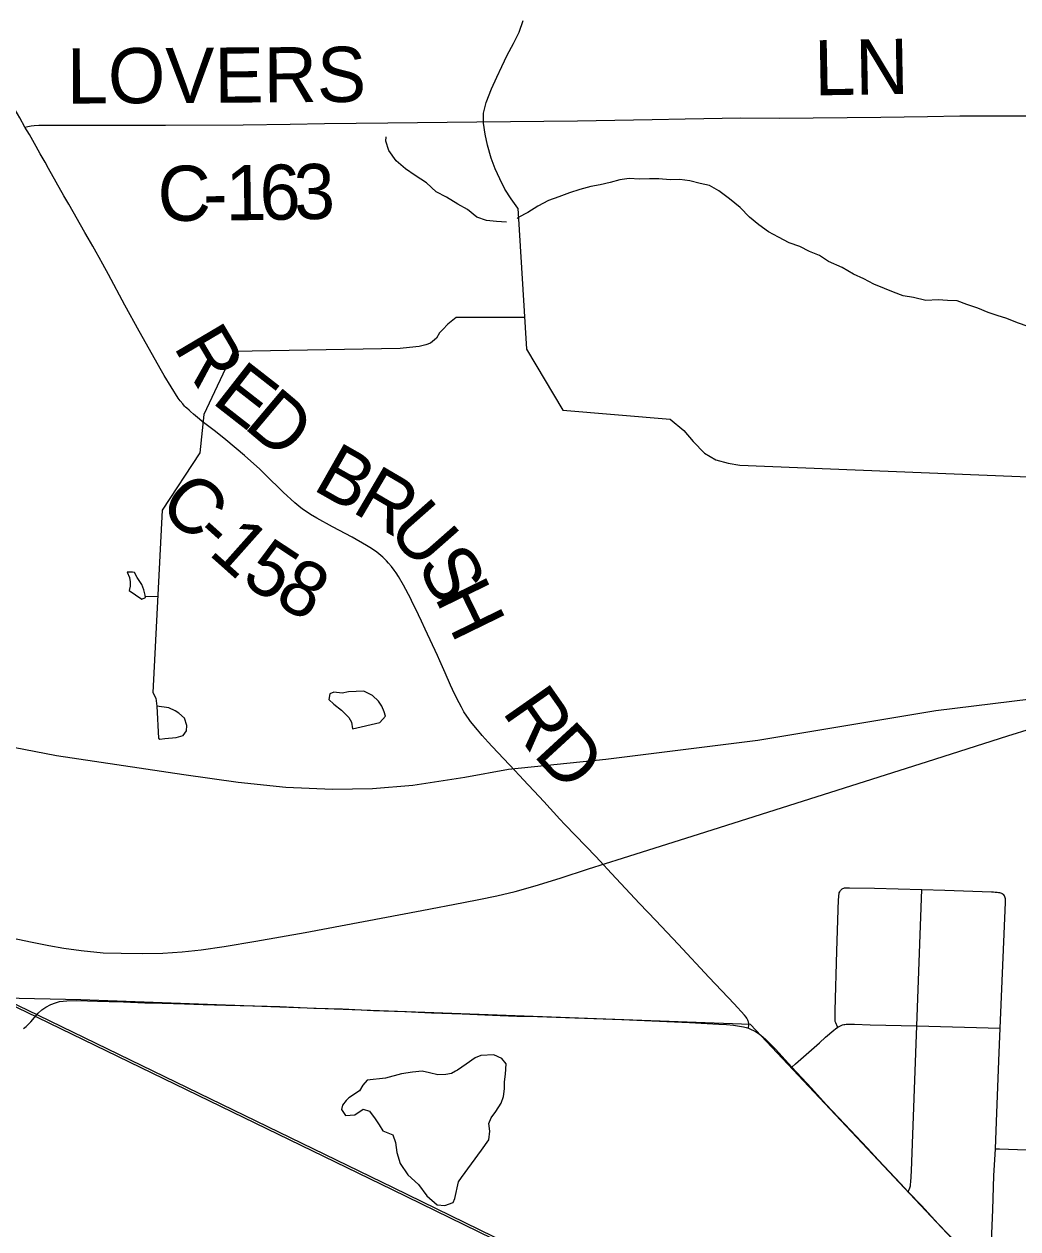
# Model space of a CAD drawing. Extents: x 0 to 34, y 0 to 22.
# Drawn here: x 5.317 to 6.341, y 14.44 to 15.681 of the extents above; entities that cross this region are included whole.
import ezdxf

# ---------------------------------------------------------------- set-up
doc = ezdxf.new("R2010")
doc.units = 0
for name, color, linetype in [('GM_X_County_Road', 7, 'Continuous'), ('GM_X_County_Road_Text', 7, 'Continuous'), ('GM_X_Minor_Lake', 7, 'Continuous'), ('GM_X_Minor_River', 7, 'Continuous'), ('GM_X_Rail_Line', 7, 'Continuous'), ('GM_X_Township_Road', 7, 'Continuous')]:
    doc.layers.add(name, color=color, linetype=linetype)

msp = doc.modelspace()

# ---------------------------------------------------------------- linework, layer by layer
at = {"layer": 'GM_X_County_Road'}
for points in [[(5.3182, 15.5753), (5.3128, 15.5847), (5.3057, 15.5971), (5.3003, 15.6068), (5.294, 15.6182), (5.2866, 15.6319), (5.2773, 15.6486), (5.261, 15.6776), (5.2575, 15.6842)], [(5.3182, 15.5753), (5.321, 15.576), (5.3244, 15.5766), (5.3277, 15.5769), (5.3323, 15.5771), (5.3412, 15.5773), (5.3605, 15.5773), (5.463, 15.5772), (5.5429, 15.5774), (5.5915, 15.5782), (5.6269, 15.5788), (5.692, 15.5797), (5.7838, 15.5806), (5.8876, 15.5817), (5.9643, 15.5831), (5.9983, 15.5838), (6.0558, 15.5848), (6.0955, 15.5846), (6.2, 15.5856), (6.2482, 15.5863), (6.2816, 15.5867), (6.3406, 15.587), (6.3728, 15.5869)], [(5.7955, 14.9418), (5.7924, 14.9451), (5.7894, 14.9485), (5.7879, 14.9501), (5.7845, 14.9542), (5.7773, 14.9631), (5.7752, 14.9659), (5.7734, 14.9684), (5.7705, 14.973), (5.7679, 14.9777), (5.7655, 14.9821), (5.7622, 14.9886), (5.7588, 14.996), (5.7567, 15.0005), (5.7513, 15.013), (5.7458, 15.0253), (5.7431, 15.031), (5.7306, 15.0582), (5.7268, 15.0664), (5.7205, 15.0794), (5.7173, 15.0859), (5.7157, 15.0893), (5.7083, 15.1033), (5.703, 15.1124), (5.7005, 15.1162), (5.6987, 15.1187), (5.6959, 15.1225), (5.6929, 15.1261), (5.6906, 15.1286), (5.6868, 15.1323), (5.6806, 15.1375), (5.6754, 15.1411), (5.6701, 15.1444), (5.6555, 15.1527), (5.6351, 15.1634), (5.6188, 15.1723), (5.6125, 15.1761), (5.6079, 15.1791), (5.6043, 15.1816), (5.6004, 15.1847), (5.5961, 15.1882), (5.5843, 15.1992), (5.5658, 15.2175), (5.5603, 15.2227), (5.5443, 15.237), (5.5252, 15.2531), (5.5145, 15.2617), (5.5009, 15.2721), (5.4981, 15.2743), (5.4918, 15.2795), (5.4888, 15.2822), (5.4872, 15.2836), (5.485, 15.2856), (5.4835, 15.2869), (5.4827, 15.2878), (5.4808, 15.29), (5.4782, 15.2931), (5.4762, 15.2959), (5.4615, 15.3195), (5.4588, 15.3241), (5.4357, 15.365), (5.4211, 15.3917), (5.4042, 15.4235), (5.3984, 15.4342), (5.3946, 15.441), (5.3916, 15.4465), (5.3881, 15.4526), (5.3833, 15.4609), (5.38, 15.4668), (5.3633, 15.4959), (5.3583, 15.5045), (5.3425, 15.5327), (5.3389, 15.5392), (5.334, 15.5477), (5.3298, 15.5552), (5.3227, 15.5675), (5.3182, 15.5753)], [(5.8274, 14.9077), (5.8231, 14.9125), (5.8175, 14.9184), (5.7996, 14.9373), (5.7955, 14.9418)], [(6.0636, 14.6469), (6.0639, 14.6504), (6.0639, 14.6519), (6.0636, 14.6535), (6.0634, 14.6544), (6.0631, 14.6553), (6.0628, 14.656), (6.0624, 14.6567), (6.062, 14.6573), (6.0612, 14.6584), (6.0596, 14.6603), (6.0488, 14.672), (6.0232, 14.6993), (5.9912, 14.7336), (5.9682, 14.7581), (5.9515, 14.7754), (5.9225, 14.8062), (5.9107, 14.8194), (5.9065, 14.8239), (5.896, 14.8344), (5.8743, 14.857), (5.8693, 14.8624), (5.8527, 14.8805), (5.8428, 14.8912), (5.8367, 14.8978), (5.8274, 14.9077)], [(5.3167, 14.6468), (5.3193, 14.6488), (5.3241, 14.6536), (5.3319, 14.6624), (5.3357, 14.6659), (5.3398, 14.6688), (5.3449, 14.6715), (5.3496, 14.6733), (5.3539, 14.6744), (5.3574, 14.675), (5.3614, 14.6753), (5.3714, 14.6757), (5.3827, 14.6752), (5.3928, 14.675), (5.405, 14.6745), (5.4198, 14.6741), (5.4416, 14.6732), (5.4596, 14.6727), (5.4826, 14.672), (5.5019, 14.6715), (5.5252, 14.6709), (5.5546, 14.6701), (5.5808, 14.6692), (5.616, 14.6678), (5.6454, 14.6668), (5.6773, 14.6653), (5.7096, 14.6641), (5.737, 14.6629), (5.7686, 14.6617), (5.8077, 14.66), (5.8251, 14.6595), (5.8462, 14.6589), (5.9332, 14.6558), (6.0028, 14.6528), (6.0332, 14.6513), (6.0412, 14.6507), (6.0481, 14.6501), (6.0524, 14.6496), (6.0564, 14.6489), (6.0587, 14.6484), (6.0612, 14.6478), (6.0636, 14.6469)], [(6.0636, 14.6469), (6.0664, 14.6457), (6.0688, 14.6446), (6.071, 14.6435), (6.0736, 14.6418), (6.0763, 14.6399), (6.0816, 14.6355), (6.0916, 14.6253), (6.1085, 14.607)], [(6.1085, 14.607), (6.1287, 14.5851), (6.1437, 14.5685), (6.1689, 14.542), (6.186, 14.5239), (6.1978, 14.5111), (6.2203, 14.4871), (6.2284, 14.4786)], [(6.2284, 14.4786), (6.2419, 14.4643), (6.2593, 14.4456), (6.2879, 14.4156), (6.3108, 14.3914)]]:
    msp.add_lwpolyline(points, dxfattribs=at)
at = {"layer": 'GM_X_Minor_Lake'}
for p, q in [((5.4257, 15.098), (5.4386, 15.089)), ((5.4542, 14.9788), (5.4556, 14.9458)), ((5.6558, 14.9553), (5.6837, 14.962)), ((5.768, 14.4931), (5.7886, 14.5214))]:
    msp.add_line(p, q, dxfattribs=at)
for points in [[(5.4386, 15.089), (5.4424, 15.0906), (5.442, 15.0932), (5.4408, 15.0985), (5.4385, 15.1042), (5.4339, 15.1113), (5.4312, 15.1163), (5.4289, 15.1166), (5.4236, 15.1166), (5.4259, 15.1113), (5.4267, 15.1067), (5.4264, 15.1022), (5.4257, 15.098)], [(5.6837, 14.962), (5.6897, 14.9685), (5.6882, 14.973), (5.6859, 14.9787), (5.6824, 14.984), (5.6763, 14.9896), (5.6672, 14.9941), (5.6517, 14.9936), (5.6449, 14.992), (5.6365, 14.9931), (5.6324, 14.9915), (5.6313, 14.9855), (5.6363, 14.9809), (5.6443, 14.9746), (5.6519, 14.967), (5.6546, 14.9621), (5.6558, 14.9553)], [(5.4556, 14.9458), (5.4571, 14.9447), (5.4624, 14.9455), (5.4738, 14.9463), (5.4813, 14.9486), (5.4847, 14.9532), (5.485, 14.9589), (5.4827, 14.9665), (5.4766, 14.9714), (5.4728, 14.974), (5.4663, 14.977), (5.4542, 14.9788)], [(5.7886, 14.5214), (5.7961, 14.532), (5.7971, 14.5408), (5.7963, 14.5487), (5.7985, 14.5548), (5.8034, 14.5613), (5.809, 14.5697), (5.8112, 14.5765), (5.8123, 14.5845), (5.8123, 14.5917), (5.8133, 14.5997), (5.814, 14.6103), (5.8094, 14.6159), (5.8014, 14.6197), (5.7878, 14.6188), (5.7822, 14.6165), (5.7727, 14.61), (5.7637, 14.6038), (5.7618, 14.6027), (5.7577, 14.6004), (5.752, 14.5992), (5.7437, 14.5988), (5.735, 14.601), (5.7274, 14.6028), (5.7176, 14.6016), (5.7062, 14.6), (5.6896, 14.5957), (5.6707, 14.5933), (5.6662, 14.5883), (5.6628, 14.5826), (5.6519, 14.5753), (5.6493, 14.5726), (5.6455, 14.5677), (5.6444, 14.5631), (5.6486, 14.5571), (5.6581, 14.5579), (5.6668, 14.5636), (5.6732, 14.5614), (5.6789, 14.5535), (5.6832, 14.5475), (5.687, 14.5414), (5.6972, 14.5373), (5.7, 14.5294), (5.7012, 14.5188), (5.7047, 14.5078), (5.7127, 14.4961), (5.7238, 14.486), (5.7322, 14.4743), (5.7428, 14.4649), (5.7508, 14.4642), (5.7595, 14.4673), (5.761, 14.4715), (5.765, 14.4886), (5.768, 14.4931)]]:
    msp.add_lwpolyline(points, dxfattribs=at)
at = {"layer": 'GM_X_Minor_River'}
for p, q in [((5.826, 15.4917), (5.8351, 15.3465)), ((5.8351, 15.3465), (5.8723, 15.2835)), ((5.8723, 15.2835), (5.9829, 15.2745)), ((5.9829, 15.2745), (5.997, 15.2628)), ((5.997, 15.2628), (6.0066, 15.2512)), ((6.0066, 15.2512), (6.0184, 15.2395)), ((6.0184, 15.2395), (6.0302, 15.2324)), ((6.0302, 15.2324), (6.0427, 15.2291)), ((6.0427, 15.2291), (6.0548, 15.2269)), ((6.0548, 15.2269), (6.4255, 15.2119))]:
    msp.add_line(p, q, dxfattribs=at)
for points in [[(5.8126, 15.5113), (5.8076, 15.5219), (5.8026, 15.5321), (5.7984, 15.5434), (5.7949, 15.5567), (5.7925, 15.568), (5.7905, 15.5794), (5.7905, 15.5896), (5.7934, 15.6006), (5.799, 15.6147), (5.8045, 15.6265), (5.8094, 15.6375), (5.815, 15.6493), (5.8217, 15.6615), (5.8273, 15.6729), (5.8317, 15.6851)], [(5.8144, 15.4772), (5.8042, 15.4779), (5.7936, 15.4789), (5.7837, 15.4823), (5.7742, 15.4902), (5.7643, 15.4958), (5.7525, 15.5029), (5.7419, 15.5085), (5.732, 15.5179), (5.7202, 15.5254), (5.7103, 15.5321), (5.7008, 15.5404), (5.6931, 15.551), (5.69, 15.5608), (5.6903, 15.5653)], [(6.352, 15.3699), (6.341, 15.3736), (6.33, 15.378), (6.3201, 15.381), (6.3106, 15.3843), (6.3, 15.3888), (6.2886, 15.3925), (6.2787, 15.3962), (6.2689, 15.3965), (6.259, 15.3972), (6.2465, 15.3967), (6.2336, 15.3997), (6.223, 15.4015), (6.2132, 15.4052), (6.2037, 15.4089), (6.193, 15.4134), (6.1824, 15.419), (6.1718, 15.4238), (6.1604, 15.4306), (6.1463, 15.4369), (6.1368, 15.4429), (6.1265, 15.447), (6.1167, 15.4522), (6.1057, 15.4559), (6.0946, 15.4619), (6.0844, 15.4675), (6.0745, 15.4747), (6.0646, 15.4825), (6.055, 15.4923), (6.044, 15.5013), (6.0333, 15.5096), (6.0234, 15.5152), (6.014, 15.517), (6.0033, 15.52), (5.9931, 15.5214), (5.9829, 15.521), (5.9715, 15.522), (5.9617, 15.5219), (5.9515, 15.5215), (5.9409, 15.5222), (5.931, 15.5209), (5.9212, 15.5182), (5.911, 15.5159), (5.9012, 15.5139), (5.8899, 15.5108), (5.8793, 15.5076), (5.8683, 15.5034), (5.8578, 15.4995), (5.8465, 15.4937), (5.8363, 15.4872), (5.8265, 15.4822), (5.8254, 15.4811)], [(5.826, 15.4917), (5.8192, 15.5015), (5.8126, 15.5113)], [(5.8331, 15.3791), (5.7626, 15.379), (5.7539, 15.3721), (5.7487, 15.3667), (5.7453, 15.3633), (5.7423, 15.3579), (5.7359, 15.3526), (5.7314, 15.351), (5.7242, 15.3491), (5.7144, 15.3483), (5.7049, 15.347), (5.5331, 15.3442), (5.5026, 15.2791), (5.4984, 15.2396), (5.4595, 15.1806), (5.45, 14.9928), (5.4529, 14.987), (5.4542, 14.9788)], [(5.4549, 15.0914), (5.4422, 15.0917)]]:
    msp.add_lwpolyline(points, dxfattribs=at)
at = {"layer": 'GM_X_Rail_Line'}
for points in [[(6.8257, 13.9299), (6.7419, 13.9706), (6.3738, 14.1502), (6.2876, 14.192), (5.697, 14.4804), (5.3198, 14.6635), (5.2954, 14.6752), (4.9919, 14.8219), (4.4345, 15.0918)], [(6.8268, 13.932), (6.743, 13.9727), (6.3748, 14.1523), (6.2886, 14.1941), (5.698, 14.4825), (5.3208, 14.6656), (5.2965, 14.6773), (4.993, 14.824), (4.4354, 15.094)], [(4.551, 15.0845), (4.5877, 15.0793), (4.6298, 15.0695), (5.0347, 14.9892), (5.3505, 14.928), (5.482, 14.9083), (5.5377, 14.9006), (5.5871, 14.8954), (5.6352, 14.8931), (5.6764, 14.8939), (5.718, 14.8975), (5.7714, 14.9056), (5.8163, 14.9137), (5.9167, 14.9242), (6.0732, 14.9436), (6.2567, 14.9742), (6.4552, 14.9985)], [(5.3061, 14.7399), (5.324, 14.7358), (5.3427, 14.7322), (5.3583, 14.7296), (5.376, 14.7272), (5.3987, 14.7248), (5.4174, 14.7243), (5.4396, 14.724), (5.4601, 14.7243), (5.4802, 14.7255), (5.4998, 14.7277), (5.5235, 14.7311), (5.5559, 14.7367), (5.607, 14.7457), (5.727, 14.7684), (5.7702, 14.7765), (5.786, 14.7796), (5.8045, 14.7834), (5.8232, 14.7879), (5.8439, 14.7937), (5.8697, 14.8016), (5.8987, 14.811), (5.9338, 14.8221), (6.0196, 14.8493), (6.2481, 14.9219), (6.331, 14.9483), (6.3798, 14.9634)], [(7.8047, 13.8173), (7.8032, 13.8784), (7.8061, 14.0853), (7.8056, 14.1774), (7.691, 14.1788), (7.619, 14.1835), (7.5106, 14.1906), (7.0652, 14.2059), (6.6818, 14.2193), (6.4657, 14.226), (6.0658, 14.6509), (5.3757, 14.6762), (5.2963, 14.6779)]]:
    msp.add_lwpolyline(points, dxfattribs=at)
at = {"layer": 'GM_X_Township_Road'}
for q in [(6.2424, 14.7899), (6.3231, 14.6471)]:
    msp.add_line((6.2373, 14.6495), q, dxfattribs=at)
for points in [[(6.1558, 14.648), (6.1551, 14.6492), (6.1547, 14.65), (6.1543, 14.6508), (6.1536, 14.6526), (6.1534, 14.6532), (6.1532, 14.654), (6.1531, 14.655), (6.153, 14.6567), (6.1529, 14.6602), (6.1529, 14.6653), (6.1548, 14.7263), (6.1566, 14.7795), (6.1567, 14.782), (6.1568, 14.7837), (6.157, 14.7853), (6.1573, 14.7864), (6.1577, 14.7874), (6.1585, 14.7888), (6.1593, 14.7896), (6.1602, 14.7904)], [(6.1602, 14.7904), (6.1611, 14.7909), (6.1618, 14.7913), (6.1626, 14.7915), (6.1639, 14.7916), (6.1652, 14.7917), (6.1661, 14.7917), (6.1677, 14.7917), (6.1936, 14.7911), (6.2424, 14.7899)], [(6.2424, 14.7899), (6.2661, 14.7893), (6.3142, 14.7875), (6.3163, 14.7874), (6.318, 14.7872), (6.3194, 14.7871), (6.3201, 14.787), (6.3212, 14.7868), (6.3223, 14.7867), (6.3234, 14.7864), (6.3243, 14.7861), (6.3251, 14.7857), (6.3263, 14.7849), (6.3269, 14.7843)], [(6.3231, 14.6471), (6.3285, 14.7765), (6.3285, 14.7781), (6.3285, 14.7791), (6.3284, 14.7802), (6.3283, 14.7813), (6.328, 14.7824), (6.3275, 14.7835), (6.3269, 14.7843)], [(6.1085, 14.607), (6.1121, 14.6102), (6.1368, 14.6319), (6.1432, 14.6376), (6.1516, 14.6449), (6.1535, 14.6464), (6.1558, 14.648)], [(6.1558, 14.648), (6.1571, 14.6489), (6.1585, 14.6496), (6.1599, 14.6501), (6.1605, 14.6503), (6.162, 14.6507), (6.163, 14.6508), (6.1644, 14.651), (6.1657, 14.651), (6.1676, 14.6511), (6.173, 14.6511), (6.189, 14.6506), (6.2373, 14.6495)], [(6.2284, 14.4786), (6.2298, 14.4825), (6.2305, 14.4845), (6.2308, 14.4863), (6.2311, 14.4885), (6.2315, 14.4942), (6.2318, 14.5001), (6.2373, 14.6495)], [(6.3181, 14.5229), (6.3193, 14.5506), (6.3216, 14.6133), (6.3231, 14.6471)], [(6.3108, 14.3914), (6.3125, 14.3992), (6.3129, 14.4013), (6.3132, 14.4028), (6.3134, 14.4046), (6.3138, 14.4113), (6.3141, 14.4163), (6.3146, 14.4351), (6.3154, 14.4601), (6.3166, 14.4948), (6.3181, 14.5229)], [(6.3181, 14.5229), (6.3222, 14.5227), (6.4055, 14.5197)]]:
    msp.add_lwpolyline(points, dxfattribs=at)

# ---------------------------------------------------------------- texts
at = {"layer": 'GM_X_County_Road_Text'}
for s, height, rotation, p in [('LN', 0.05682, 1.0317, (6.132, 15.6078)), ('LOVERS', 0.05682, 0.3519, (5.3616, 15.5994)), ('3', 0.0568, 1.3824, (5.5959, 15.48)), ('C', 0.0568, 0.5816, (5.4551, 15.4784)), ('1', 0.0568, 0.6491, (5.5252, 15.4791)), ('6', 0.0568, 0.833, (5.5603, 15.4795)), ('-', 0.0568, 0.5858, (5.5018, 15.4788)), ('R', 0.0568, 300.6231, (5.4705, 15.3493)), ('E', 0.0568, 322.0428, (5.5093, 15.2921)), ('D', 0.0568, 319.8717, (5.5423, 15.2663)), ('B', 0.0568, 330.3824, (5.6133, 15.2025)), ('R', 0.0568, 329.5885, (5.6537, 15.1795)), ('C', 0.0568, 317.982, (5.4538, 15.1829)), ('U', 0.0568, 311.3682, (5.6903, 15.1589)), ('-', 0.0568, 318.0314, (5.4886, 15.1516)), ('1', 0.0568, 318.3042, (5.5061, 15.1358)), ('5', 0.0568, 326.6636, (5.5394, 15.1071)), ('S', 0.0568, 299.0648, (5.7215, 15.124)), ('8', 0.0568, 331.7215, (5.5734, 15.085)), ('H', 0.0568, 295.9916, (5.7397, 15.0912)), ('R', 0.0568, 304.9891, (5.809, 14.973)), ('D', 0.0568, 312.6175, (5.8409, 14.9284))]:
    msp.add_text(s, height=height, rotation=rotation, dxfattribs=at).set_placement(p)

doc.saveas('drawing.dxf')
